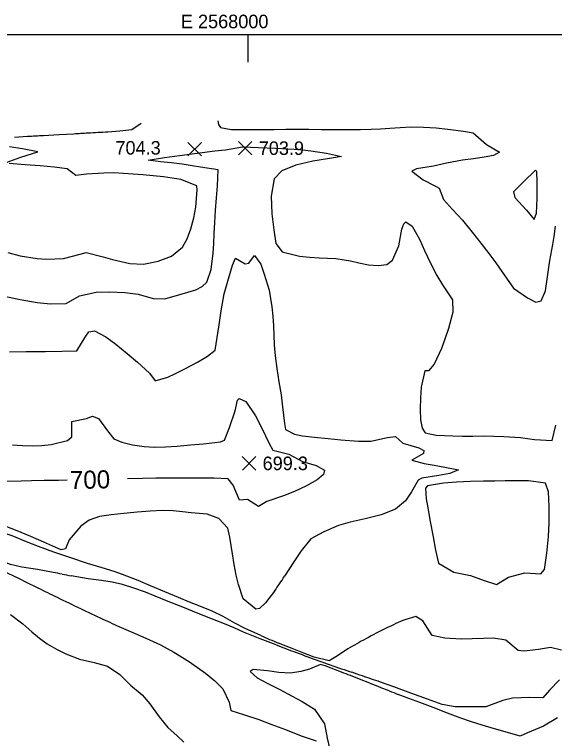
# Model space of a CAD drawing. Extents: x 2566079 to 2571326, y 424054 to 426896.
# Drawn here: x 2567741 to 2568340, y 426094 to 426896 of the extents above; entities that cross this region are included whole.
import ezdxf

# ---------------------------------------------------------------- set-up
doc = ezdxf.new("R2010")
doc.units = 0
for name, color, linetype in [('Contour_ADS_Label_Major', 7, 'Continuous'), ('Contour_ADS_Major', 7, 'Continuous'), ('Contour_ADS_Minor', 7, 'Continuous'), ('Contour_ADS_Spot_Elevation', 7, 'Continuous'), ('Contour_ADS_State_Plane_Border', 7, 'Continuous')]:
    doc.layers.add(name, color=color, linetype=linetype)

# ---------------------------------------------------------------- blocks, each defined once
blk = doc.blocks.new('S750')
at = {"layer": 'Contour_ADS_Spot_Elevation'}
for p, q in [((-0.5, 0.498), (0.5, -0.498)), ((-0.498, -0.5), (0.498, 0.5))]:
    blk.add_line(p, q, dxfattribs=at)

msp = doc.modelspace()

# ---------------------------------------------------------------- linework, layer by layer
at = {"layer": 'Contour_ADS_Major'}
msp.add_line((2567882.99, 426382.09), (2567866.37, 426381.75), dxfattribs=at)
for points in [[(2567739.05, 426419.5), (2567749.91, 426418.72), (2567760.69, 426418.42), (2567771.39, 426418.69), (2567781.9, 426419.6), (2567800.02, 426424.09), (2567804.79, 426428.44), (2567804.74, 426445.42), (2567820.99, 426448.61), (2567827.71, 426451.07), (2567834.43, 426448.74), (2567844.09, 426435.08), (2567851.31, 426426.07), (2567860.31, 426422.27), (2567872.1, 426419.26), (2567884.7, 426417.37), (2567896.62, 426416.76), (2567908.51, 426417.14), (2567921.55, 426418.1), (2567936.29, 426419.25), (2567950.79, 426420.45), (2567969.46, 426422.59), (2567974.03, 426424.5), (2567979.3, 426438.57), (2567985.81, 426456.94), (2567988.44, 426468.77), (2567990.29, 426470.66), (2567997.65, 426467.47), (2568008.34, 426451.46), (2568015.17, 426437.97), (2568023.49, 426420.95), (2568027.53, 426413.56), (2568045.28, 426408.98), (2568060.49, 426400.85), (2568075.52, 426396.64), (2568084.71, 426391.15), (2568083.76, 426386.54), (2568076.51, 426380.51), (2568064.87, 426373.88), (2568051.62, 426367.74), (2568039.21, 426362.91), (2568020.81, 426356.42), (2568011.4, 426351.05), (2567999.33, 426358.65), (2567990.46, 426358.21), (2567983.64, 426374.6), (2567978.13, 426381.75), (2567961.91, 426382.6), (2567951.72, 426382.57), (2567941.11, 426382.52), (2567921.36, 426382.49), (2567910.53, 426382.44), (2567897.8, 426382.31), (2567882.99, 426382.09)], [(2567799.73, 426380.17), (2567790.05, 426379.98), (2567773.98, 426379.73), (2567760.06, 426379.51), (2567748.41, 426379.26), (2567729.86, 426378.59)]]:
    msp.add_lwpolyline(points, dxfattribs=at)
at = {"layer": 'Contour_ADS_Minor'}
for p, q in [((2567741.17, 426760.6), (2567755.68, 426761.41)), ((2568156.48, 426146.68), (2568146.56, 426150.57))]:
    msp.add_line(p, q, dxfattribs=at)
for points in [[(2567966.69, 426778.42), (2567967.35, 426774.46), (2567969.42, 426771.21), (2567981.14, 426769.11), (2567991.24, 426768.84), (2568003.06, 426768.83), (2568015.77, 426768.93), (2568028.86, 426769.08), (2568041.87, 426769.2), (2568054.55, 426769.25), (2568067.38, 426769.22), (2568081.05, 426769.14), (2568095.88, 426769.03), (2568110.88, 426768.98), (2568124.7, 426769.07), (2568136.43, 426769.37), (2568146.87, 426769.87), (2568157.24, 426770.53), (2568168.55, 426771.27), (2568180.94, 426771.76), (2568194.32, 426771.63), (2568208.33, 426770.64), (2568221.49, 426769.19), (2568238.78, 426766.95), (2568249.39, 426765.25), (2568264.15, 426752.3), (2568278.69, 426743.77), (2568271.9, 426739.97), (2568261.71, 426738.31), (2568249.67, 426736.62), (2568237.82, 426734.82), (2568220.07, 426731.54), (2568205.61, 426728.22), (2568186.66, 426725.24), (2568181.52, 426722.87), (2568193.98, 426713.07), (2568207.86, 426706.2), (2568211.9, 426703.81), (2568216.77, 426691.38), (2568226.46, 426680.1), (2568237.83, 426668.36), (2568249.97, 426653.42), (2568258.14, 426642.95), (2568266.85, 426631.62), (2568274.65, 426621.17), (2568284.42, 426606.91), (2568294.25, 426592.91), (2568309.52, 426582.31), (2568318.84, 426577.69), (2568324.79, 426578.94), (2568329.51, 426590.03), (2568332.28, 426608.39), (2568334.52, 426623.56), (2568337.74, 426641.62), (2568339.12, 426650.3), (2568340.83, 426661.92)], [(2567844.67, 426766.46), (2567857.77, 426767.32), (2567871.06, 426769.05), (2567881.51, 426776.13)], [(2567773.23, 426762.39), (2567790.78, 426763.38), (2567806.79, 426764.29)], [(2567728.22, 426584.49), (2567747.65, 426580.49), (2567766.32, 426577.24), (2567780.94, 426575.52), (2567798.35, 426575.93), (2567813.23, 426584.52), (2567831.63, 426588.69), (2567846.88, 426589.04), (2567863.54, 426588.16), (2567878.15, 426586.28), (2567895, 426581.44), (2567907.82, 426581.1), (2567924.57, 426585.87), (2567942.19, 426591.25), (2567949.27, 426594.9), (2567954.2, 426599.84), (2567959.23, 426613.62), (2567961.33, 426632.01), (2567961.96, 426642.54), (2567962.55, 426653.78), (2567963.22, 426665.88), (2567964.05, 426679.05), (2567965.09, 426693.13), (2567966.12, 426706.33), (2567966.95, 426724.31), (2567947.24, 426727.38), (2567937.9, 426728.84), (2567926.83, 426730.51), (2567914.84, 426732.05), (2567903.01, 426733.18), (2567889.2, 426734.86), (2567907.5, 426737.97), (2567924, 426740.01), (2567943.47, 426742.82), (2567963.07, 426745.19), (2567974.83, 426746.43), (2567994.02, 426749.76), (2568011.42, 426749.16), (2568030.33, 426748.18), (2568044.07, 426747.57), (2568057.8, 426746.7), (2568069.59, 426745.49), (2568086.92, 426742.67), (2568103.5, 426738.9), (2568088.06, 426736.34), (2568071.76, 426733.77), (2568053.13, 426729.51), (2568037.53, 426723.02), (2568028.98, 426714.15), (2568025.7, 426695.23), (2568026.4, 426675.49), (2568028.41, 426657.91), (2568030.7, 426642.53), (2568037.88, 426633.49), (2568056.92, 426628.5), (2568068.28, 426627.29), (2568078.94, 426626.82), (2568097.41, 426626.14), (2568113.49, 426623.19), (2568122.62, 426621.08), (2568133.31, 426619.03), (2568144.26, 426618.09), (2568153.66, 426619.47), (2568160.2, 426624.01), (2568166.92, 426640.07), (2568170.56, 426658.3), (2568172.53, 426664.31), (2568175.02, 426666.47), (2568181.99, 426661.8), (2568190.38, 426646.52), (2568195.68, 426634.96), (2568202.36, 426620.79), (2568209.28, 426607.17), (2568215.47, 426596.62), (2568226.75, 426580.16), (2568226.84, 426566.43), (2568222.21, 426548.54), (2568218.62, 426537.5), (2568214.53, 426526.36), (2568206.37, 426508.91), (2568199.88, 426501.52), (2568195.83, 426501.28), (2568191.79, 426483.4), (2568190.93, 426471.63), (2568190.58, 426458.89), (2568191.11, 426446.98), (2568192.93, 426437.78)], [(2567731.91, 426732.44), (2567748.19, 426738.36), (2567766.99, 426744.26), (2567750.01, 426747.43), (2567735.7, 426749.77)], [(2567733.94, 426632.57), (2567747.41, 426628.8), (2567766.47, 426625.87), (2567776.77, 426625.19), (2567795.53, 426626.09), (2567813.97, 426630.91), (2567820.68, 426632.63), (2567839.29, 426627.88), (2567849.94, 426624.83), (2567869.09, 426620.27), (2567884.06, 426619.77), (2567900.29, 426623.07), (2567915.35, 426628.41), (2567927.35, 426638.64), (2567932.37, 426647.67), (2567936.63, 426658.8), (2567939.95, 426670.95), (2567942.22, 426683.03), (2567943.79, 426701.93), (2567943.2, 426706.65), (2567925.47, 426713.4), (2567906.12, 426716.39), (2567894.85, 426717.54), (2567883.52, 426718.58), (2567872.7, 426719.57), (2567862.14, 426720.36), (2567851.4, 426720.78), (2567840.3, 426720.69), (2567821.1, 426719.51), (2567809.33, 426717.89), (2567799.39, 426725.24), (2567785.15, 426727.38), (2567769.64, 426728.7), (2567753.18, 426729.87), (2567735.26, 426731.27)], [(2567775.46, 426523.03), (2567793.76, 426523.28), (2567810.14, 426523.51), (2567819.4, 426538.76), (2567823.52, 426544.55), (2567829.83, 426545.81), (2567842.25, 426539.28), (2567853.4, 426530.84), (2567865.99, 426520.55), (2567877.42, 426510.88), (2567890.82, 426498.94), (2567897.03, 426490.19), (2567910.95, 426494.42), (2567918.69, 426497.95), (2567930.57, 426504), (2567943.87, 426511.19), (2567955, 426517.64), (2567963.7, 426524.42), (2567965.82, 426538.33), (2567967.88, 426552.56), (2567970.27, 426568), (2567973.4, 426586.89), (2567978.21, 426603.5), (2567982.68, 426618.62), (2567986.17, 426626.28), (2567996.89, 426620.12), (2568000.92, 426620.8), (2568007.3, 426629.45), (2568014.17, 426619.73), (2568018.03, 426608.45), (2568023.39, 426590.94), (2568026.49, 426572.31), (2568027.38, 426562.13), (2568028.04, 426551.33), (2568028.41, 426540.85), (2568028.86, 426530.09), (2568029.89, 426518.06), (2568031.81, 426504.14), (2568034.23, 426489.25), (2568036.56, 426474.69), (2568038.35, 426461.66), (2568040.39, 426443.1), (2568040.39, 426443.1)], [(2567735.53, 426522.64), (2567753.99, 426522.78)], [(2568040.39, 426443.1), (2568041.66, 426436.21), (2568051.48, 426431.4), (2568060.49, 426429.55), (2568073.62, 426427.83), (2568088.67, 426426.31), (2568102.8, 426425.04), (2568122.25, 426423.45), (2568135.94, 426423.64), (2568154.66, 426427.41), (2568163.32, 426428.72), (2568171.55, 426421.3), (2568189.08, 426416.01), (2568194.89, 426413.21), (2568194.47, 426409.95), (2568181.52, 426402.38), (2568195.02, 426398.65), (2568206.41, 426396.72), (2568218.05, 426394.8), (2568233.08, 426391.55), (2568223.7, 426387.61), (2568211.4, 426385.42), (2568192.57, 426382.32), (2568188.47, 426380.17), (2568181.16, 426367.28), (2568174.31, 426357.36), (2568163.36, 426348.21), (2568147.69, 426341.73), (2568129.84, 426337.27), (2568113.16, 426333.62), (2568100.25, 426329.81), (2568083.86, 426322.87), (2568069.4, 426315.01), (2568058.77, 426301.8), (2568050.8, 426289.78), (2568040.38, 426273.71)], [(2568192.93, 426437.78), (2568196.4, 426432.62), (2568208.48, 426429.93), (2568226.9, 426429.29), (2568237.72, 426429.13), (2568249.13, 426429.15), (2568260.79, 426429.21), (2568272.37, 426429.13), (2568283.49, 426428.8), (2568301.78, 426427.58), (2568317.31, 426425.33), (2568336.83, 426424.38), (2568341.14, 426441.1)], [(2568029.2, 426257.02), (2568019.44, 426244.07), (2568012.73, 426238.01), (2568008.67, 426237.16), (2567994.67, 426248.5), (2567989.35, 426264.5), (2567986.98, 426275.07), (2567984.66, 426286.78), (2567982.63, 426298.45), (2567979.73, 426317.05), (2567977.62, 426327.08), (2567967.77, 426337.6), (2567954.51, 426342.37), (2567936.89, 426344), (2567927.33, 426345.11), (2567916.95, 426346.19), (2567905.19, 426346.61), (2567891.7, 426345.95), (2567877.16, 426344.61), (2567862.47, 426343.18), (2567848.45, 426341.94), (2567835.54, 426339.98), (2567824.11, 426336.03), (2567814.51, 426329.38), (2567801.92, 426314.15), (2567797.64, 426303.93), (2567792.86, 426303.04), (2567783.69, 426307.2), (2567773.85, 426311.64), (2567759.19, 426317.92), (2567742.13, 426324.92), (2567725.89, 426331.26)], [(2568014.15, 426207.92), (2567996.8, 426215.66), (2567985.22, 426221.54), (2567972.59, 426229.14), (2567960.08, 426234.99), (2567944.64, 426241.19), (2567934.97, 426245.11), (2567922.77, 426250.15), (2567907.73, 426256.46), (2567891.99, 426263.09), (2567878.38, 426268.83), (2567860.77, 426275.82), (2567851.45, 426278.88), (2567838.34, 426282.91), (2567821.98, 426287.98), (2567803.67, 426293.95), (2567784.86, 426300.54), (2567767.69, 426306.87), (2567754.48, 426311.92), (2567738.55, 426318.56), (2567721.92, 426324.22), (2567721.92, 426324.22)], [(2567783.98, 426277.93), (2567766.83, 426281.13), (2567749.22, 426283.8), (2567736.59, 426286.73), (2567720.23, 426292.91), (2567708.45, 426296.59), (2567705.51, 426293.76), (2567716.85, 426284.8), (2567733, 426277.37), (2567746.39, 426271.11), (2567753.43, 426267.6), (2567766.94, 426260.94)], [(2568031.21, 426197.54), (2568013.33, 426204.4), (2567994.82, 426211.71), (2567984.44, 426216.47), (2567975.63, 426220.17), (2567960.58, 426226.25), (2567942.94, 426233.27), (2567927.68, 426239.31), (2567911.62, 426245.72), (2567897.15, 426251.67), (2567886.35, 426255.96), (2567873.56, 426260.67), (2567860.78, 426264.65), (2567849.3, 426267.12), (2567837.43, 426268.83), (2567822.76, 426270.93), (2567803.97, 426274.18)], [(2567736.63, 426231.22), (2567750.32, 426220.82), (2567760.56, 426212.24), (2567768.84, 426205.12), (2567777.34, 426198.79), (2567787.57, 426192.8), (2567798.18, 426187.58), (2567813.12, 426181.68), (2567829.47, 426178.16), (2567844.26, 426173.88), (2567857.81, 426164.86), (2567869.57, 426153.1), (2567882.51, 426142.44), (2567890.99, 426132.25), (2567901.38, 426117.84), (2567911.21, 426105.96), (2567921.34, 426096.73), (2567928.79, 426089.82)], [(2568347.4, 426191.76), (2568335.04, 426194.6), (2568321.96, 426192.34), (2568306.14, 426190.75), (2568299.28, 426191.47), (2568285.84, 426202.75), (2568272.1, 426204.96), (2568260.93, 426204.79), (2568248.29, 426204.29), (2568236.1, 426204.03), (2568217.93, 426205.24), (2568204.1, 426207.94), (2568193.66, 426224.16), (2568185.77, 426229.12), (2568173.9, 426225.56)], [(2567859.45, 426216.94), (2567874.95, 426210.2), (2567886.63, 426205.19), (2567902.82, 426197.6), (2567917.72, 426189.39), (2567934.14, 426179.74), (2567944.05, 426172.71), (2567952.93, 426166.17), (2567963.36, 426157.73), (2567972.2, 426148.83), (2567979.01, 426134.04), (2567980.77, 426124.79), (2567995.12, 426120.38), (2568011.95, 426114.73), (2568025.42, 426109.65), (2568041.33, 426103.97), (2568059.03, 426096.92), (2568075.56, 426091.2)], [(2568110.66, 426193.14), (2568099.05, 426185.52), (2568089.72, 426180.05), (2568073.13, 426183.97), (2568061.66, 426188.29), (2568050.73, 426192.7), (2568033.73, 426199.67)], [(2568103.71, 426167.38), (2568085.34, 426174.47), (2568080.21, 426175.93), (2568067.94, 426170.87), (2568058.62, 426167.96), (2568047.09, 426166.38), (2568034.12, 426167.02), (2568021.57, 426168.85), (2568005.8, 426170.42), (2568002.32, 426167.98), (2568010.09, 426161.13), (2568021.18, 426155.22), (2568035.15, 426148.01), (2568048.9, 426140.9), (2568059.94, 426135.01), (2568073.69, 426126.43), (2568084.81, 426110.25), (2568087.74, 426094.4), (2568090.25, 426083.3), (2568092.24, 426080.74)], [(2568135.01, 426155.1), (2568123.47, 426159.63), (2568113.59, 426163.51)], [(2568345.27, 426158.85), (2568334.14, 426147.42), (2568326.54, 426138.96), (2568312.11, 426139.12), (2568293.13, 426138.66), (2568282.25, 426135.88), (2568263.58, 426129.07), (2568245.47, 426129.06), (2568229.36, 426129.07), (2568215.27, 426131.44), (2568198.97, 426137.48), (2568180.27, 426144.04), (2568161.61, 426151.01), (2568146.62, 426156.37)], [(2568342.96, 426116.63), (2568327.46, 426107.64), (2568309.7, 426099.99), (2568301.37, 426096.46), (2568285.02, 426101.12), (2568273.29, 426104.58), (2568259.61, 426108.66), (2568246.52, 426112.74), (2568235.89, 426116.35), (2568217.94, 426123.18), (2568208.04, 426126.99), (2568190.36, 426133.67), (2568178.31, 426138.18), (2568166.41, 426142.8)]]:
    msp.add_lwpolyline(points, dxfattribs=at)
for points in [[(2568319.48, 426676.05), (2568320.22, 426692.4), (2568320.47, 426710.79), (2568319.93, 426722.58), (2568318.39, 426724.02), (2568305.23, 426710.79), (2568294.11, 426699.97), (2568295.75, 426693.5), (2568308.4, 426679.38), (2568316.9, 426669.12), (2568319.48, 426676.05)], [(2568246.63, 426378.58), (2568231.12, 426377.96), (2568216.47, 426377.03), (2568198.92, 426373.83), (2568196.62, 426371.52), (2568197.51, 426359.5), (2568199.23, 426349.52), (2568202, 426334.46), (2568205.14, 426317.48), (2568207.79, 426302.73), (2568210.9, 426288.19), (2568227.93, 426278.2), (2568246.66, 426274.7), (2568261.49, 426269.14), (2568275.39, 426264.42), (2568288.53, 426272.66), (2568306.79, 426277.5), (2568324.35, 426276.29), (2568328.43, 426281.12), (2568331.14, 426299.15), (2568332.9, 426317.73), (2568333.69, 426332.76), (2568333.58, 426350.89), (2568333.12, 426367.19), (2568329.48, 426376.89), (2568310.83, 426379.59), (2568294.42, 426379.41), (2568284.76, 426379.32), (2568273.63, 426379.19), (2568260.93, 426378.96), (2568246.63, 426378.58)]]:
    msp.add_lwpolyline(points, close=True, dxfattribs=at)
for centre, radius, start, end in [((2565537.18, 466648.26), 39948.5, 273.183497, 273.208708), ((2566267.17, 453975.63), 27254.86, 273.238344, 273.272033), ((2566268.85, 453844.72), 27124.07, 273.284269, 273.307417), ((2567712.49, 428966.46), 2203.97, 273.15341, 273.43828), ((2567700.91, 431351.98), 4829.49, 270.62978, 270.7572), ((2567652.91, 437001.48), 10479.17, 270.611411, 270.670083), ((2564425.67, 408309.37), 18279.7, 79.381731, 79.413586), ((2568065.71, 427693.96), 1443.7, 259.15076, 259.55458), ((2567378.97, 426704.67), 789.43, 325.45434, 326.91239), ((2570531.87, 431884.61), 6266.62, 243.818531, 244.037172), ((2569734.87, 430238.6), 4437.81, 243.98509, 244.35431), ((2568849.31, 428394.04), 2391.68, 244.35395, 245.01674), ((2568429.67, 427500.85), 1404.84, 245.14451, 246.05276), ((2568293.4, 425937.02), 312.31, 112.49633, 116.54213), ((2568400.44, 425709.61), 563.61, 115.94682, 118.61096), ((2568612.21, 427599.96), 1515.07, 246.7502, 247.55371), ((2568344.82, 425802.71), 455.26, 118.0764, 120.95318), ((2569072.93, 428933.55), 2927.61, 249.15597, 249.62579), ((2568888.83, 428435.08), 2396.24, 249.60287, 250.23449), ((2569074.65, 428974.4), 2966.63, 250.3795, 250.89149), ((2569325.96, 429706.84), 3740.98, 250.92693, 251.11578), ((2566745.97, 422686.57), 3736.24, 68.52834, 68.69106), ((2561301.26, 406335.28), 20969.86, 71.004508, 71.038197), ((2564451.38, 415491.69), 11286.73, 70.889125, 70.995467), ((2577903.72, 451045.08), 26738.33, 248.571208, 248.597794), ((2569964.42, 430759.05), 4954.05, 248.59602, 248.71932)]:
    msp.add_arc(centre, radius, start, end, dxfattribs=at)
at = {"layer": 'Contour_ADS_State_Plane_Border'}
msp.add_line((2568000, 426843.74), (2568000, 426873.74), dxfattribs=at)
msp.add_lwpolyline([(2566079.33, 424077.11), (2571302.93, 424077.11), (2571302.93, 426873.74), (2566079.33, 426873.74), (2566079.33, 424077.11)], close=True, dxfattribs=at)

# ---------------------------------------------------------------- block references
at = {"layer": 'Contour_ADS_Spot_Elevation', "xscale": 15, "yscale": 15}
for p in [(2567940.89, 426747.14), (2567996.84, 426748.28), (2568001.14, 426398.85)]:
    msp.add_blockref('S750', p, dxfattribs=at)

# ---------------------------------------------------------------- texts
at = {"layer": 'Contour_ADS_Label_Major'}
msp.add_text('700', height=20, rotation=1.36225, dxfattribs=at).set_placement((2567802.78, 426370.24))
at = {"layer": 'Contour_ADS_Spot_Elevation'}
for s, p in [('704.3', (2567853.02, 426741.17)), ('703.9', (2568011.84, 426740.78)), ('699.3', (2568016.14, 426391.35))]:
    msp.add_text(s, height=15, dxfattribs=at).set_placement(p)
at = {"layer": 'Contour_ADS_State_Plane_Border'}
msp.add_text(' E 2568000', height=15, dxfattribs=at).set_placement((2567920, 426881.24))

doc.saveas('drawing.dxf')
